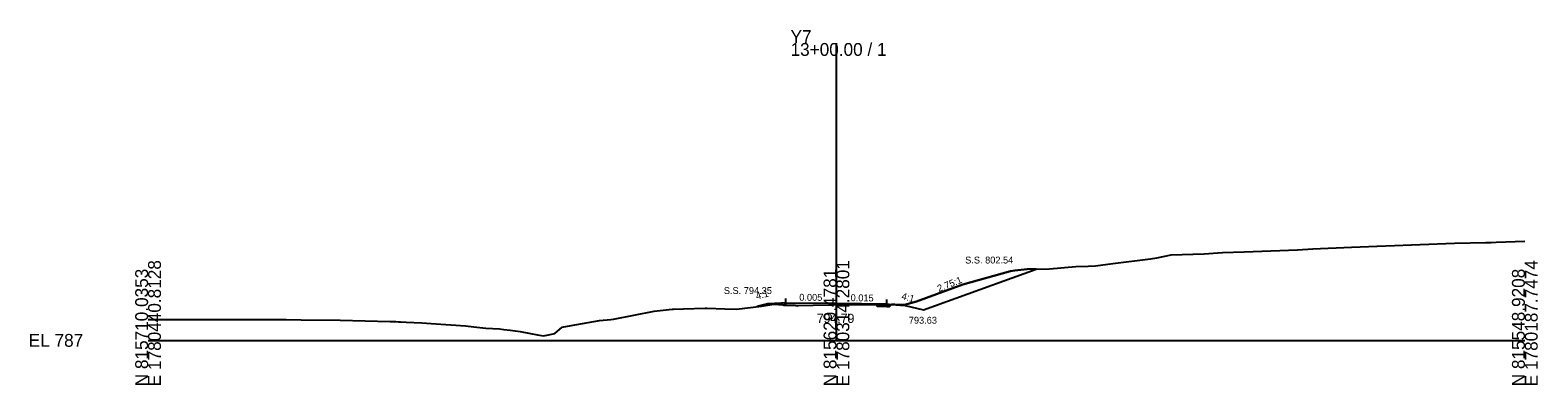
# Model space of a CAD drawing. Extents: x -26 to 2903, y -10 to 5536.
# Drawn here: x -25.7 to 302.8, y 2990.3 to 3067.6 of the extents above; entities that cross this region are included whole.
import ezdxf

# ---------------------------------------------------------------- set-up
doc = ezdxf.new("R2010")
doc.units = 0
for name, color, linetype in [('Exist Cross Section Cell', 7, 'Continuous'), ('Exist XS Center Line Elevation Label', 7, 'Continuous'), ('Exist XS Ground Line', 7, 'Continuous'), ('Prop XS Ditch Slope Text', 7, 'Continuous'), ('Prop XS Ditch Standard Text', 7, 'Continuous'), ('Prop XS Dump Level', 7, 'Continuous'), ('Prop XS Earthwork Shape', 7, 'Continuous'), ('Prop XS EOT Tick Mark', 7, 'Continuous'), ('Prop XS Finish Grade', 7, 'Continuous'), ('Prop XS Finish Grade Earthwork', 7, 'Continuous'), ('Prop XS Finish Grade Pavement', 7, 'Continuous'), ('Prop XS Pvmt Edge Slope', 7, 'Continuous'), ('Prop XS SE Text', 7, 'Continuous'), ('Prop XS Side Slope Text', 7, 'Continuous'), ('Prop XS SS Elevation Text', 7, 'Continuous'), ('Prop XS Subgrade Earthwork', 7, 'Continuous')]:
    doc.layers.add(name, color=color, linetype=linetype)

msp = doc.modelspace()

# ---------------------------------------------------------------- linework, layer by layer
at = {"layer": 'Exist Cross Section Cell'}
for p, q in [((150, 3000), (150, 3064.79)), ((0, 3000), (150, 3000)), ((150, 3000), (300, 3000))]:
    msp.add_line(p, q, dxfattribs=at)
at = {"layer": 'Exist XS Ground Line'}
for p, q in [((234.12, 3019.12), (238.85, 3019.27)), ((238.85, 3019.27), (250.5, 3019.7)), ((250.5, 3019.7), (253.78, 3019.92)), ((253.78, 3019.92), (262.2, 3020.29)), ((262.2, 3020.29), (284.7, 3021.21)), ((284.7, 3021.21), (291.47, 3021.31)), ((291.47, 3021.31), (292.69, 3021.3)), ((292.69, 3021.3), (293.79, 3021.37)), ((293.79, 3021.37), (300, 3021.6)), ((196.43, 3015.59), (202.19, 3016.07)), ((202.19, 3016.07), (204.82, 3016.14)), ((204.82, 3016.14), (206.46, 3016.25)), ((206.46, 3016.25), (210.21, 3016.72)), ((210.21, 3016.72), (218.41, 3017.74)), ((218.41, 3017.74), (219.84, 3017.99)), ((219.84, 3017.99), (222.92, 3018.66)), ((222.92, 3018.66), (230.1, 3018.88)), ((230.1, 3018.88), (234.12, 3019.12)), ((177.51, 3012.16), (187.95, 3015.06)), ((187.95, 3015.06), (188.85, 3015.23)), ((188.85, 3015.23), (191.53, 3015.51)), ((191.53, 3015.51), (196.43, 3015.59)), ((167.44, 3008.5), (177.51, 3012.16)), ((101.45, 3004.65), (110.27, 3006.35)), ((110.27, 3006.35), (114.2, 3006.77)), ((114.2, 3006.77), (114.52, 3006.78)), ((114.52, 3006.78), (116.65, 3006.86)), ((116.65, 3006.86), (121.4, 3007)), ((121.4, 3007), (121.86, 3006.98)), ((121.86, 3006.98), (125.66, 3006.88)), ((125.66, 3006.88), (128.21, 3006.8)), ((128.21, 3006.8), (133.68, 3007.47)), ((133.68, 3007.47), (136.38, 3007.86)), ((136.38, 3007.86), (139.15, 3007.73)), ((139.15, 3007.73), (141.05, 3007.6)), ((141.05, 3007.6), (148.79, 3007.77)), ((148.79, 3007.77), (150.06, 3007.8)), ((150.06, 3007.8), (154.59, 3007.81)), ((154.59, 3007.81), (158.87, 3007.81)), ((158.87, 3007.81), (160.81, 3007.83)), ((160.81, 3007.83), (161.2, 3007.83)), ((161.2, 3007.83), (161.94, 3007.82)), ((161.94, 3007.82), (164.85, 3007.76)), ((164.85, 3007.76), (167.44, 3008.5)), ((0, 3004.52), (6.31, 3004.53)), ((6.31, 3004.53), (9.04, 3004.52)), ((9.04, 3004.52), (13.16, 3004.53)), ((13.16, 3004.53), (20.37, 3004.54)), ((20.37, 3004.54), (25.39, 3004.55)), ((25.39, 3004.55), (30.1, 3004.56)), ((30.1, 3004.56), (33.33, 3004.5)), ((33.33, 3004.5), (41.84, 3004.37)), ((41.84, 3004.37), (52.74, 3004.12)), ((52.74, 3004.12), (54.02, 3004.09)), ((54.02, 3004.09), (54.55, 3004.06)), ((54.55, 3004.06), (55.02, 3004.05)), ((55.02, 3004.05), (56.22, 3003.99)), ((56.22, 3003.99), (59.63, 3003.83)), ((59.63, 3003.83), (61.69, 3003.65)), ((61.69, 3003.65), (69.2, 3003.15)), ((69.2, 3003.15), (70.99, 3002.93)), ((70.99, 3002.93), (73.6, 3002.68)), ((88.67, 3001.48), (90.21, 3002.91)), ((90.21, 3002.91), (92.2, 3003.26)), ((92.2, 3003.26), (98.38, 3004.3)), ((98.38, 3004.3), (100.81, 3004.56)), ((100.81, 3004.56), (101.45, 3004.65)), ((73.6, 3002.68), (76.61, 3002.51)), ((76.61, 3002.51), (77.56, 3002.39)), ((77.56, 3002.39), (78.92, 3002.19)), ((78.92, 3002.19), (81.1, 3001.9)), ((81.1, 3001.9), (83.36, 3001.49)), ((83.36, 3001.49), (84.83, 3001.23)), ((84.83, 3001.23), (86.19, 3001)), ((86.19, 3001), (87.26, 3001.2)), ((87.26, 3001.2), (88.67, 3001.48))]:
    msp.add_line(p, q, dxfattribs=at)
at = {"layer": 'Prop XS Dump Level'}
for p, q in [((139, 3008.15), (150, 3008.1)), ((150, 3008.1), (161, 3007.93))]:
    msp.add_line(p, q, dxfattribs=at)
at = {"layer": 'Prop XS Earthwork Shape'}
for points in [[(169, 3006.63), (193.5, 3015.54), (191.53, 3015.51), (188.85, 3015.23), (187.95, 3015.06), (177.51, 3012.16), (167.44, 3008.5), (164.85, 3007.76), (162.71, 3007.8), (165, 3007.63)], [(132.67, 3007.35), (133.68, 3007.47), (136.38, 3007.86), (138.3, 3007.77), (137.98, 3008.1), (135, 3007.93)], [(138.46, 3007.61), (138.3, 3007.77), (139.15, 3007.73), (141.05, 3007.6), (139, 3007.61)], [(161.94, 3007.82), (161.99, 3007.82), (161.55, 3007.38), (161, 3007.39), (158.87, 3007.42), (158.87, 3007.81), (160.81, 3007.83), (161.2, 3007.83)], [(161.99, 3007.82), (162.71, 3007.8), (162.02, 3007.85)]]:
    msp.add_lwpolyline(points, close=True, dxfattribs=at)
at = {"layer": 'Prop XS EOT Tick Mark'}
for p, q in [((139, 3008.15), (139, 3009.15)), ((161, 3007.93), (161, 3008.93))]:
    msp.add_line(p, q, dxfattribs=at)
at = {"layer": 'Prop XS Finish Grade'}
for p, q in [((139, 3008.15), (137.98, 3008.1)), ((161, 3007.93), (162.02, 3007.85))]:
    msp.add_line(p, q, dxfattribs=at)
at = {"layer": 'Prop XS Finish Grade Earthwork'}
for p, q in [((169, 3006.63), (193.5, 3015.54)), ((135, 3007.93), (132.67, 3007.35)), ((137.98, 3008.1), (135, 3007.93)), ((162.02, 3007.85), (165, 3007.63)), ((165, 3007.63), (169, 3006.63))]:
    msp.add_line(p, q, dxfattribs=at)
at = {"layer": 'Prop XS Finish Grade Pavement'}
for p, q in [((139, 3008.15), (150, 3008.1)), ((150, 3008.1), (161, 3007.93))]:
    msp.add_line(p, q, dxfattribs=at)
at = {"layer": 'Prop XS Pvmt Edge Slope'}
for p, q in [((139, 3008.15), (138.46, 3007.61)), ((161, 3007.93), (161.55, 3007.38))]:
    msp.add_line(p, q, dxfattribs=at)
at = {"layer": 'Prop XS Subgrade Earthwork'}
for p, q in [((138.46, 3007.61), (137.98, 3008.1)), ((139, 3007.61), (138.46, 3007.61)), ((141.05, 3007.6), (139, 3007.61)), ((141.05, 3007.6), (141.05, 3007.6)), ((158.87, 3007.42), (158.87, 3007.81)), ((158.87, 3007.42), (161, 3007.39)), ((161, 3007.39), (161.55, 3007.38)), ((161.55, 3007.38), (162.02, 3007.85))]:
    msp.add_line(p, q, dxfattribs=at)

# ---------------------------------------------------------------- texts
at = {"layer": 'Exist Cross Section Cell'}
for s, p in [('Y7', (140, 3064.79)), ('13+00.00 / 1', (140, 3061.99)), ('EL 787', (-26, 2998.6))]:
    msp.add_text(s, height=2.8, dxfattribs=at).set_placement(p)
for s, p in [('E 1780440.8128', (2.8, 2990)), ('E 1780314.2801', (152.8, 2990)), ('E 1780187.7474', (302.8, 2990)), ('N 815710.0353', (0, 2990)), ('N 815629.4781', (150, 2990)), ('N 815548.9208', (300, 2990))]:
    msp.add_text(s, height=2.8, rotation=90, dxfattribs=at).set_placement(p)
at = {"layer": 'Exist XS Center Line Elevation Label'}
msp.add_text('794.79', height=2, dxfattribs=at).set_placement((145.73, 3003.79))
at = {"layer": 'Prop XS Ditch Slope Text'}
for rotation, p in [(14.0362, (132.64, 3008.89)), (345.9638, (164.08, 3008.97))]:
    msp.add_text('4:1', height=1.5, rotation=rotation, dxfattribs=at).set_placement(p)
at = {"layer": 'Prop XS Ditch Standard Text'}
msp.add_text('793.63', height=1.5, dxfattribs=at).set_placement((165.77, 3003.63))
at = {"layer": 'Prop XS Dump Level'}
for s, height, p in [('Case1', 0.04, (135, 3007.89)), ('Eop', 0.3, (141.05, 3007.3)), ('Eop', 0.3, (158.87, 3007.51)), ('Case1', 0.04, (165, 3007.59))]:
    msp.add_text(s, height=height, dxfattribs=at).set_placement(p)
at = {"layer": 'Prop XS SE Text'}
for s, rotation, p in [('0.005', 359.7135, (141.9, 3008.64)), ('0.015', 359.1406, (153.08, 3008.55))]:
    msp.add_text(s, height=1.5, rotation=rotation, dxfattribs=at).set_placement(p)
at = {"layer": 'Prop XS Side Slope Text'}
msp.add_text('2.75:1', height=1.5, rotation=21.7099, dxfattribs=at).set_placement((172.33, 3010.53))
at = {"layer": 'Prop XS SS Elevation Text'}
for s, p in [('S.S. 802.54', (178.05, 3016.75)), ('S.S. 794.35', (125.46, 3010.1))]:
    msp.add_text(s, height=1.5, dxfattribs=at).set_placement(p)

doc.saveas('drawing.dxf')
